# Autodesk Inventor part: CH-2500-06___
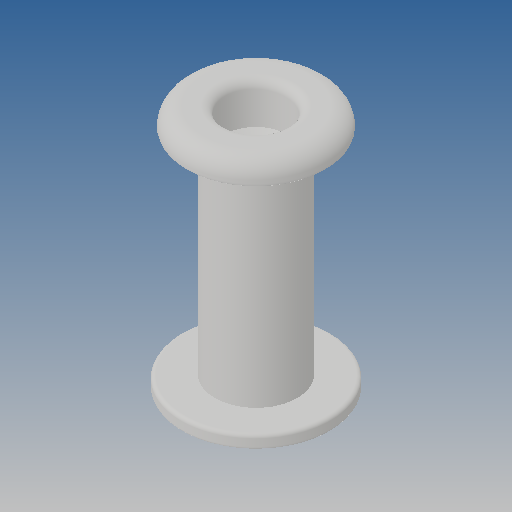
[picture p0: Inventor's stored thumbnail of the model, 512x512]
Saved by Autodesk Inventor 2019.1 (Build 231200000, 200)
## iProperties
Created: 2012-09
Part Number: CH-2500-06___
Material: Ogólny
Document SubType Name: Modeling
Designer: CADENGINEERING4
Density: 1 g/cm^3
Appearance: Domyślna
Author: CADENGINEERING4
Revision Number: ÈÎºÎ
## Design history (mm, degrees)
feature "NONE"
node "Bryła1"
